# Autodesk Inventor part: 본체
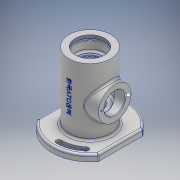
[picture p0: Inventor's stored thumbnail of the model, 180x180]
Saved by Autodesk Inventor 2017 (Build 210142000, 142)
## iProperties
Part Number: 본체
Material: 알루미늄 6061
Document SubType Name: Modeling
Designer: MRC
Density: 2.7 g/cm^3
Appearance: 알루미늄 - 평지
Mass: 691.902 g
Surface Area: 628.287 cm^2
Volume: 256.26 cm^3
Author: MRC
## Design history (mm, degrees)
sketch "스케치1"
  geometry: C1 r 32 at (0, 0); 1 further point
  constraints: 1 centre point, 1 coincident
  dimensions: "d0" = 64 diameter of C1
extrude "돌출1" new body sketch "스케치1" stored distance "d1" = 102; taper "d2" = 0 deg
sketch "스케치2"
  geometry: C1 r 58 at (0, 0); 1 further point
  constraints: 1 centre point, 1 coincident
  dimensions: "d3" = 116 diameter of C1
extrude "돌출2" join sketch "스케치2" distance "d4" = 10; taper "d5" = 0 deg
sketch "스케치4"
  geometry: L1 (47, -58)-(-47, -58); L2 (-47, -58)-(-47, 58); L3 (-47, 58)-(47, 58); L4 (47, 58)-(47, -58); L5 (47, -58)-(-47, 58); L6 (-47, -58)-(47, 58); L7 (-47, 58)-(-58.255, 58); L8 (-58.255, 58)-(-58.255, -58); L9 (-58.255, -58)-(-47, -58); L10 (47, -58)-(58.255, -58); L11 (58.255, -58)-(58.255, 58); L12 (58.255, 58)-(47, 58); 1 further point
  constraints: 24 end point, 4 perpendicular, 3 horizontal, 3 parallel, 2 midpoint
  dimensions: "d8" = 94 distance of L2.end L3.end; "d9" = 116 distance between parallel lines of L3 L1; "d10" = 11.25538 distance between parallel lines of L2 L8; "d11" = 11.255 distance between parallel lines of L4 L11
extrude "돌출3" cut sketch "스케치4" distance "d12" = 13; taper "d13" = 0 deg
sketch "스케치5"
  geometry: C1 r 36 at (0, 0); 1 further point
  constraints: 1 centre point, 1 coincident
  dimensions: "d14" = 72 diameter of C1
extrude "돌출4" join sketch "스케치5" distance "d15" = 3; taper "d16" = 0 deg
sketch "스케치6"
  geometry: C1 r 22.5 at (0, 0); 1 further point
  constraints: 1 centre point, 1 coincident
  dimensions: "d17" = 45 diameter of C1
extrude "돌출5" cut sketch "스케치6" distance "d18" = 8; taper "d19" = 0 deg
sketch "스케치7"
  geometry: C1 r 24 at (0, 0); 1 further point
  constraints: 1 centre point, 1 coincident
  dimensions: "d20" = 48 diameter of C1
extrude "돌출6" cut sketch "스케치7" distance "d21" = 3; taper "d22" = 0 deg
sketch "스케치9"
  geometry: C1 r 22.5 at (0, 0); 1 further point
  constraints: 1 centre point, 1 coincident
  dimensions: "d23" = 45 diameter of C1
extrude "돌출7" cut sketch "스케치9" distance "d24" = 22; taper "d25" = 0 deg
sketch "스케치10"
  geometry: C1 r 17.5 at (0, 0); 1 further point
  constraints: 1 centre point, 1 coincident
  dimensions: "d26" = 35 diameter of C1
extrude "돌출8" cut sketch "스케치10" distance "d27" = 4; taper "d28" = 0 deg
sketch "스케치12"
  geometry: C1 r 18.5 at (0, 0); 1 further point
  constraints: 1 centre point, 1 coincident
  dimensions: "d30" = 37 diameter of C1
extrude "돌출9" cut sketch "스케치12" distance "d31" = 1.75; taper "d32" = 0 deg
sketch "스케치13"
  geometry: C1 r 17.5 at (0, 0); 1 further point
  constraints: 1 centre point, 1 coincident
  dimensions: "d33" = 35 diameter of C1
extrude "돌출10" cut sketch "스케치13" distance "d34" = 11; taper "d35" = 0 deg
sketch "스케치14"
  geometry: C1 r 27 at (0, 0); 1 further point
  constraints: 1 centre point, 1 coincident
  dimensions: "d36" = 54 diameter of C1
extrude "돌출11" cut sketch "스케치14" distance "d37" = 38; taper "d38" = 0 deg
sketch "스케치15"
  geometry: C1 r 17.5 at (0, 0); 1 further point
  constraints: 1 centre point, 1 coincident
  dimensions: "d39" = 35 diameter of C1
extrude "돌출12" cut sketch "스케치15" distance "d40" = 11; taper "d41" = 0 deg
sketch "스케치16"
  geometry: C1 r 15 at (0, 0); 1 further point
  constraints: 1 centre point, 1 coincident
  dimensions: "d42" = 30 diameter of C1
extrude "돌출13" cut sketch "스케치16" distance "d43" = 5; taper "d44" = 0 deg
sketch "스케치17"
  geometry: C1 r 11 at (0, 0); 1 further point
  constraints: 1 centre point, 1 coincident
  dimensions: "d45" = 22 diameter of C1
extrude "돌출14" cut sketch "스케치17" distance "d46" = 30; taper "d47" = 0 deg
sketch "스케치18"
  geometry: L1 (36, -61)-(36, -64) reference; L2 (36, -64)-(11, -64) reference; L3 (11, -64)-(11, -40) reference; L4 (11, -40)-(15, -40) reference; L5 (15, -40)-(15, -35) reference; L6 (15, -35)-(17.5, -35) reference; L7 (17.5, -35)-(17.5, -24) reference; L8 (17.5, -24)-(27, -24) reference; L9 (27, -24)-(27, 14) reference; L10 (27, 14)-(17.5, 14) reference; L11 (17.5, 14)-(17.5, 25) reference; L12 (17.5, 25)-(18.5, 25) reference; L13 (18.5, 25)-(18.5, 26.75) reference; L14 (18.5, 26.75)-(17.5, 26.75) reference; L15 (17.5, 26.75)-(17.5, 29) reference; L16 (17.5, 29)-(22.5, 29) reference; L17 (22.5, 29)-(22.5, 43) reference; L18 (22.5, 43)-(24, 43) reference; L19 (24, 43)-(24, 46) reference; L20 (24, 46)-(22.5, 46) reference; L21 (22.5, 51)-(32, 51) reference; L22 (32, 51)-(32, -51) reference; L23 (32, -51)-(58, -51) reference; L24 (58, -51)-(58, -61) reference; L25 (58, -61)-(36, -61) reference; L26 (-58, -51)-(-32, -51) reference; L27 (-32, -51)-(-32, 51) reference; L28 (-32, 51)-(-22.5, 51) reference; L29 (-22.5, 46)-(-24, 46) reference; L30 (-24, 46)-(-24, 43) reference; L31 (-24, 43)-(-22.5, 43) reference; L32 (-22.5, 43)-(-22.5, 29) reference; L33 (-22.5, 29)-(-17.5, 29) reference; L34 (-17.5, 29)-(-17.5, 26.75) reference; L35 (-17.5, 26.75)-(-18.5, 26.75) reference; L36 (-18.5, 26.75)-(-18.5, 25) reference; L37 (-18.5, 25)-(-17.5, 25) reference; L38 (-17.5, 25)-(-17.5, 14) reference; L39 (-17.5, 14)-(-27, 14) reference; L40 (-27, 14)-(-27, -24) reference; L41 (-27, -24)-(-17.5, -24) reference; L42 (-17.5, -24)-(-17.5, -35) reference; L43 (-17.5, -35)-(-15, -35) reference; L44 (-15, -35)-(-15, -40) reference; L45 (-15, -40)-(-11, -40) reference; L46 (-11, -40)-(-11, -64) reference; L47 (-11, -64)-(-36, -64) reference; L48 (-36, -64)-(-36, -61) reference; L49 (-36, -61)-(-58, -61) reference; L50 (-58, -61)-(-58, -51) reference; L51 (-22.5, 51)-(22.5, 51) reference; L52 (0, 51)-(0, -64); L53 (-36, -64)-(36, -64) reference; L54 (0, -50)-(-20, -50); L55 (-20, -50)-(-30, -64); L56 (-15, -50)-(-15, -42.7); L57 (-15, -42.7)-(0, -42.7); L58 (22.5, 46)-(22.5, 51) reference; L59 (-22.5, 51)-(-22.5, 46) reference; 1 further point
  constraints: 10 end point, 4 point on line, 2 midpoint, 1 horizontal, 1 perpendicular, 1 vertical
  dimensions: "d49" = 40 diameter of L54.end L52; "d50" = 60 diameter of L55.end L52; "d51" = 14 distance between parallel lines of L53 L54; "d52" = 7.3 distance of L56.start L56.end; "d53" = 30 diameter of L56 L52
revolve "회전1" sketch "스케치18" stored, may be unused: angle "d54" = 90 deg
node "작업 평면1"
sketch "스케치20"
  geometry: L1 (32, 51)-(-32, 51) reference; C1 r 25 at (0, -5); 2 further points
  constraints: 1 centre point, 1 coincident, 1 midpoint, 1 vertical alignment
  dimensions: "d56" = 50 diameter of C1; "d134" = 56 distance from line of L1 point (0, -5)
extrude "돌출15" join sketch "스케치20" stored distance "d57" = 30; taper "d58" = 0 deg
sketch "스케치23"
  geometry: L1 (0, 0)-(30.854, -36.77); L2 (0, 0)-(0, -48); L3 (0, 0)-(-30.854, 36.77); L4 (0, 0)-(0, 48); C1 r 4 at (30.854, -36.77); A1 r 48 centre (0, 0) between (30.854, -36.77) and (0, -48); A2 r 48 centre (0, 0) between (0, -48) and (30.854, -36.77); A3 r 52 centre (0, 0) between (0, -52) and (33.425, -39.834); A4 r 44 centre (0, 0) between (0, -44) and (28.283, -33.706); A5 r 4 centre (0, -48) between (0, -44) and (0, -52); A6 r 4 centre (30.854, -36.77) between (33.425, -39.834) and (28.283, -33.706); A7 r 48 centre (0, 0) between (0, 48) and (-30.854, 36.77); A8 r 52 centre (0, 0) between (0, 52) and (-33.425, 39.834); A9 r 44 centre (0, 0) between (0, 44) and (-28.283, 33.706); A10 r 4 centre (0, 48) between (0, 44) and (0, 52); A11 r 4 centre (-30.854, 36.77) between (-33.425, 39.834) and (-28.283, 33.706); 1 further point
  constraints: 23 point on circle, 12 centre point, 8 end point, 8 tangent, 3 coincident, 1 collinear, 1 concentric, 1 vertical
  dimensions: "d71" = 96 diameter of A1; "d72" = 8 diameter of C1; "d73" = 40 deg angle of L2 L1; "d74" = 8 diameter of A5; "d77" = 8 diameter of A10; "d79" = 40 deg angle of L3 L4
extrude "돌출17" cut sketch "스케치23" distance "d75" = 4.4; taper "d76" = 0 deg
sketch "스케치24"
  geometry: L1 (47, 33.985)-(47, -33.985) reference; L2 (-47, -33.985)-(-47, 33.985) reference; C1 r 23.857 at (0, 0) reference; C2 r 4 at (-30.854, 36.77); C3 r 4 at (30.854, -36.77); A1 r 4 centre (-30.854, 36.77) between (-33.425, 39.834) and (-28.283, 33.706) reference; A2 r 44 centre (0, 0) between (0, 44) and (-28.283, 33.706) reference; A3 r 4 centre (0, 48) between (0, 44) and (0, 52) reference; A4 r 52 centre (0, 0) between (0, 52) and (-33.425, 39.834) reference; A5 r 4 centre (30.854, -36.77) between (33.425, -39.834) and (28.283, -33.706) reference; A6 r 44 centre (0, 0) between (0, -44) and (28.283, -33.706) reference; A7 r 4 centre (0, -48) between (0, -44) and (0, -52) reference; A8 r 52 centre (0, 0) between (0, -52) and (33.425, -39.834) reference; A9 r 58 centre (0, 0) between (-47, -33.985) and (47, -33.985) reference; A10 r 58 centre (0, 0) between (47, 33.985) and (-47, 33.985) reference; 1 further point
  constraints: 2 centre point, 2 coincident
  dimensions: "d80" = 8 diameter of C2; "d81" = 8 diameter of C3
extrude "돌출18" cut sketch "스케치24" stored distance "d82" = 4.4; taper "d83" = 0 deg
sketch "스케치25"
  geometry: L1 (47, 33.985)-(47, -33.985) reference; L2 (-47, -33.985)-(-47, 33.985) reference; C1 r 23.857 at (0, 0) reference; A1 r 4 centre (-30.854, 36.77) between (-28.283, 33.706) and (-33.425, 39.834) reference; A2 r 4 centre (-30.854, 36.77) between (-33.425, 39.834) and (-28.283, 33.706) reference; A3 r 44 centre (0, 0) between (0, 44) and (-28.283, 33.706) reference; A4 r 4 centre (0, 48) between (0, 44) and (0, 52) reference; A5 r 52 centre (0, 0) between (0, 52) and (-33.425, 39.834) reference; A6 r 4 centre (30.854, -36.77) between (28.283, -33.706) and (33.425, -39.834) reference; A7 r 4 centre (30.854, -36.77) between (33.425, -39.834) and (28.283, -33.706) reference; A8 r 44 centre (0, 0) between (0, -44) and (28.283, -33.706) reference; A9 r 4 centre (0, -48) between (0, -44) and (0, -52) reference; A10 r 52 centre (0, 0) between (0, -52) and (33.425, -39.834) reference; A11 r 58 centre (0, 0) between (-47, -33.985) and (47, -33.985) reference; A12 r 58 centre (0, 0) between (47, 33.985) and (-47, 33.985) reference; A13 r 48 centre (0, 0) between (0, 48) and (-30.854, 36.77); A14 r 50.25 centre (0, 0) between (0, 50.25) and (-32.3, 38.494); A15 r 45.75 centre (0, 0) between (0, 45.75) and (-29.408, 35.047); A16 r 2.25 centre (0, 48) between (0, 45.75) and (0, 50.25); A17 r 2.25 centre (-30.854, 36.77) between (-32.3, 38.494) and (-29.408, 35.047); A18 r 48 centre (0, 0) between (0, -48) and (30.854, -36.77); A19 r 50.25 centre (0, 0) between (0, -50.25) and (32.3, -38.494); A20 r 45.75 centre (0, 0) between (0, -45.75) and (29.408, -35.047); A21 r 2.25 centre (0, -48) between (0, -45.75) and (0, -50.25); A22 r 2.25 centre (30.854, -36.77) between (32.3, -38.494) and (29.408, -35.047); 1 further point
  constraints: 20 point on circle, 10 centre point, 8 tangent, 2 coincident
  dimensions: "d84" = 4.5 diameter of A16; "d85" = 4.5 diameter of A21
extrude "돌출19" cut sketch "스케치25" stored distance "d86" = 4.4; taper "d87" = 0 deg
sketch "스케치29"
  geometry: C1 r 25 at (0, 0); C2 r 25 at (0, 0) reference; 1 further point
  constraints: 2 coincident, 1 centre point
  dimensions: "d94" = 50 diameter of C1
extrude "돌출20" join sketch "스케치29" stored distance "d95" = 4.4; taper "d96" = 5 deg
feature "스레드1" dims "d109" = 8, "d110" = 0
fillet "모깎기1" dims "d111" = 3
chamfer "모따기1" distance "d112" = 1; stored, may be unused: second distance "d113" = 2, angle "d114" = 45 deg
chamfer "모따기2" distance "d115" = 1; stored, may be unused: second distance "d116" = 2, angle "d117" = 45 deg
fillet "모깎기2" dims "d118" = 3
chamfer "모따기3" distance "d119" = 1; stored, may be unused: second distance "d120" = 2, angle "d121" = 45 deg
fillet "모깎기3" dims "d122" = 0.6
fillet "모깎기4" dims "d123" = 3
fillet "모깎기5" dims "d124" = 0.5
chamfer "모따기4" distance "d125" = 0.7; stored, may be unused: second distance "d126" = 2, angle "d127" = 30 deg
fillet "모깎기6" dims "d128" = 3
node "작업 평면3"
sketch "스케치32"
  geometry: L1 (-47, -61)-(47, -61) reference; L2 (38, 20)-(38, -30) reference; 2 further points
  constraints: 1 vertical alignment, 1 other
  dimensions: "d130" = 62 distance from line of L1 point (0, 1)
feature "엠보싱1" sketch "스케치32" dims "d8" = 94, "d9" = 116, "d10" = 11.25538, "d11" = 11.255, "d132" = 0.5, "d133" = 0
sketch "스케치34"
  geometry: C1 r 25 at (0, 0) reference; C2 r 16 at (0, 0); 1 further point
  constraints: 1 centre point, 1 coincident
  dimensions: "d135" = 32 diameter of C2
extrude "돌출22" cut sketch "스케치34" stored distance "d136" = 4.4; taper "d137" = 0 deg
sketch "스케치35" dims "d138" = 41
  geometry: C1 r 25 at (0, 0) reference; 3 further points
  constraints: 2 vertical alignment, 1 coincident, 2 other
hole "구멍3" sketch "스케치35" at (0, 20.5) diameter "d139" = 2.459; stored, may be unused: countersink angle "d143" = 90 deg, drill point angle "d145" = 118 deg; dims "d140" = 6, "d141" = 4, "d142" = 2, "d144" = 8
chamfer "모따기5" distance "d147" = 1; stored, may be unused: second distance "d148" = 2, angle "d149" = 30 deg
fillet "모깎기7" dims "d150" = 3
fillet "모깎기8" dims "d151" = 3
fillet "모깎기9" dims "d152" = 3
node "솔리드1"
mirror "미러3"
node "절단 모서리 투영1"
node "절단 모서리 투영2"
node "절단 모서리 투영3"
other parameters: "d55" = 38, "d129" = -39, "d146" = 0
